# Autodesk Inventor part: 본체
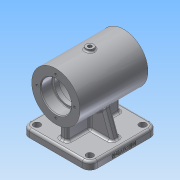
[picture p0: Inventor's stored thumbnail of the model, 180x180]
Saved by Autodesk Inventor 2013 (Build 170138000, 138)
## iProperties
Created: 2019-06
Part Number: 본체
Material: 알루미늄 6061
Document SubType Name: Modeling
Designer: Administrator
Density: 2.71 g/cm^3
Mass: 612.634 g
Surface Area: 622.719 cm^2
Volume: 226.064 cm^3
Author: Administrator
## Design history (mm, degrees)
sketch "스케치1"
  geometry: C1 r 32 at (0, 0); 1 further point
  constraints: 1 centre point, 1 coincident
  dimensions: "d0" = 64 diameter of C1
extrude "돌출1" new body sketch "스케치1" stored distance "d1" = 90; taper "d2" = 0 deg
sketch "스케치2"
  geometry: C1 r 32 at (0, 0) reference; C2 r 20 at (0, 0)
  constraints: 1 centre point, 1 coincident
  dimensions: "d3" = 40 diameter of C2
extrude "돌출2" cut sketch "스케치2" distance "d4" = 15; taper "d5" = 0 deg
sketch "스케치4"
  geometry: C1 r 20 at (0, 0) reference; C2 r 17 at (0, 0)
  constraints: 1 centre point, 1 coincident
  dimensions: "d9" = 34 diameter of C2
extrude "돌출4" cut sketch "스케치4" distance "d10" = 6; taper "d11" = 0 deg
sketch "스케치5"
  geometry: C1 r 17 at (0, 0) reference; C2 r 25 at (0, 0)
  constraints: 1 centre point, 1 coincident
  dimensions: "d12" = 50 diameter of C2
extrude "돌출5" cut sketch "스케치5" distance "d13" = 48; taper "d14" = 0 deg
fillet "모깎기1" dims "d15" = 0.6
fillet "모깎기2" dims "d16" = 3
chamfer "모따기1" distance "d17" = 1; stored, may be unused: second distance "d18" = 2, angle "d19" = 45 deg
node "작업 평면1"
sketch "스케치6"
  geometry: L1 (-45, 45)-(45, 45); L2 (45, 45)-(45, -45); L3 (45, -45)-(-45, -45); L4 (-45, -45)-(-45, 45); L5 (-45, 45)-(45, -45); L6 (45, 45)-(-45, -45); 1 further point
  constraints: 12 end point, 2 midpoint, 2 parallel, 1 horizontal, 1 perpendicular
  dimensions: "d21" = 90 distance of L2.end L3.end; "d22" = 90 distance of L1.end L2.end
extrude "돌출6" join sketch "스케치6" distance "d23" = 10; taper "d24" = 0 deg
fillet "모깎기3" dims "d25" = 10
sketch "스케치7"
  geometry: L1 (-5, -35)-(5, -35); L2 (5, -35)-(5, 35); L3 (5, 35)-(-5, 35); L4 (-5, 35)-(-5, -35); L5 (-5, -35)-(5, 35); L6 (5, -35)-(-5, 35); 1 further point
  constraints: 12 end point, 2 midpoint, 2 parallel, 1 horizontal, 1 perpendicular
  dimensions: "d26" = 10 distance of L3.end L2.end; "d27" = 70 distance of L2.end L1.end
extrude "돌출7" join sketch "스케치7" stored distance "d28" = 10; taper "d29" = 0 deg
sketch "스케치8"
  geometry: L1 (45, -65)-(-45, -65) reference; L2 (-45, -65)-(-45, -55) reference; L3 (-45, -55)-(-5, -55) reference; L4 (-5, -55)-(-5, -31.607) reference; L5 (5, -31.607)-(5, -55) reference; L6 (5, -55)-(45, -55) reference; L7 (45, -55)-(45, -65) reference; L8 (35, -55)-(29.005, -38.529); L9 (35, -55)-(52.528, -55); C1 r 25 at (0, 0) reference; A1 r 32 centre (0, 0) between (5, -31.607) and (-5, -31.607) reference; 1 further point
  constraints: 4 end point, 1 equal length, 1 horizontal, 1 point on line
  dimensions: "d30" = 110 deg angle of L9 L8; "d31" = 10 distance of L6.end L8.start
feature "리브1" sketch "스케치8" dims "d32" = 1, "d33" = 10, "d34" = 0, "d35" = 0, "d36" = 1, "d37" = 1
node "작업 평면2"
sketch "스케치9"
  geometry: C1 r 5 at (0, 0); 1 further point
  constraints: 1 centre point, 1 coincident
  dimensions: "d39" = 10 diameter of C1
extrude "돌출8" join sketch "스케치9" stored distance "d40" = 10; taper "d41" = 0 deg
fillet "모깎기4" dims "d42" = 2
hole "구멍1" diameter "d45" = 4.917; stored, may be unused: countersink angle "d49" = 90 deg, drill point angle "d51" = 118 deg; dims "d43" = 10, "d44" = 10, "d46" = 6, "d47" = 4, "d48" = 2, "d50" = 8
sketch "스케치10"
  geometry: C1 r 32 at (0, 0) reference; 1 further point
  constraints: 1 vertical alignment
  dimensions: "d52" = 25 distance of C1.centre point (0, 25)
hole "구멍2" sketch "스케치10" at (0, 25) diameter "d53" = 3.242; stored, may be unused: countersink angle "d57" = 90 deg, drill point angle "d59" = 118 deg; dims "d54" = 7, "d55" = 4, "d56" = 2, "d58" = 9
sketch "스케치11"
  geometry: A1 r 10 centre (35, 35) between (45, 35) and (35, 45) reference; A2 r 10 centre (-35, 35) between (-35, 45) and (-45, 35) reference; A3 r 10 centre (-35, -35) between (-45, -35) and (-35, -45) reference; A4 r 10 centre (35, -35) between (35, -45) and (45, -35) reference; 5 further points
  constraints: 4 coincident
hole "구멍3" sketch "스케치11" at (-35, 35), (-35, -35), (35, -35), (35, 35) diameter "d63" = 9; stored, may be unused: countersink angle "d67" = 90 deg, drill point angle "d69" = 118 deg; dims "d64" = 7, "d65" = 4, "d66" = 2, "d68" = 9
sketch "스케치12"
  geometry: L1 (45, -35)-(45, 35) reference; L2 (35, 45)-(-35, 45) reference; L3 (-45, 35)-(-45, -35) reference; L4 (-35, -45)-(35, -45) reference; L5 (-26.34, 40)-(26.34, 40); L6 (40, 26.34)-(40, -26.34); L7 (26.34, -40)-(-26.34, -40); L8 (-40, -26.34)-(-40, 26.34); L9 (-40, 40)-(40, -40); L10 (40, 40)-(-40, -40); C1 r 4.5 at (35, 35) reference; A1 r 10 centre (35, 35) between (45, 35) and (35, 45) reference; A2 r 10 centre (-35, 35) between (-35, 45) and (-45, 35) reference; A3 r 10 centre (-35, -35) between (-45, -35) and (-35, -45) reference; A4 r 10 centre (35, -35) between (35, -45) and (45, -35) reference; A5 r 10 centre (-35, 35) between (-40, 26.34) and (-26.34, 40); A6 r 10 centre (-35, -35) between (-26.34, -40) and (-40, -26.34); A7 r 10 centre (35, -35) between (40, -26.34) and (26.34, -40); A8 r 10 centre (35, 35) between (26.34, 40) and (40, 26.34); 1 further point
  constraints: 16 end point, 8 point on circle, 4 centre point, 4 coincident, 4 concentric, 2 midpoint, 2 parallel, 1 horizontal, 1 perpendicular
  dimensions: "d70" = 80 distance of L9.end L10.end; "d71" = 80 distance of L10.start L9.end; "d72" = 10 radius of A8; "d75" = 5 distance between parallel lines of L5 L2; "d76" = 5 distance between parallel lines of L3 L8; "d77" = 5 distance between parallel lines of L4 L7; "d78" = 5 distance between parallel lines of L1 L6
extrude "돌출9" cut sketch "스케치12" distance "d79" = 5; taper "d80" = 0 deg
fillet "모깎기5" dims "d81" = 3
fillet "모깎기6" dims "d82" = 3
fillet "모깎기7" dims "d83" = 3
sketch "스케치13"
  geometry: L1 (-10, 7)-(-10, 0) reference; L2 (0, 0)-(-10, 0) reference; 2 further points
  constraints: 1 other
  dimensions: "d84" = 45 distance from line of point (35, 4) L1; "d85" = 4 distance from line of point (35, 4) L2
feature "엠보싱1" sketch "스케치13" dims "d14" = 0, "d86" = 0.5, "d87" = 0
node "솔리드1"
mirror "대칭2"
mirror "대칭3"
pattern_circular "원형 패턴1" dims angle "d61" = 360 deg
mirror "대칭4"
node "절단 모서리 투영1"
other parameters: "d20" = -65
